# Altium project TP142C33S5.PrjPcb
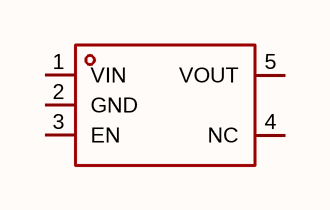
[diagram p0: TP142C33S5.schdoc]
1 sheet, 1 parts. Net scope: global (net labels, ports and power ports of the same name join across sheets).

## Sheet TP142C33S5.schdoc
size 127 x 101 mm

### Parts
U?  tp142c33s5  [SOT-23-5_L2.9-W1.6-P0.95-LS2.8-BR]  (value not drawn)

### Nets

Not connected (* = marked no-connect by the designer): U? 1(VIN) 2(GND) 3(EN) 4(NC) 5(VOUT)

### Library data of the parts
U? = tp142c33s5: 输出极性:正极;工作电压:5.5V;输出电压:3.3V;输出电流:450mA;电源纹波抑制比(PSRR):80dB@(100Hz);输出类型:固定;; Manufacturer: TECH PUBLIC(台舟); AddInBom: yes; ModelId: 7ba65df16e7b4570af156e925f9c37fe; ModelTransform: 114.173,114.173,0,90,0,0,0,0,0; Output Configuration: 正极; Voltage - Supply: 5.5V; Output Voltage: 3.3V; Output Current: 450mA; Voltage Dropout: 180mV@(300mA); standby current: 2uA; Noise: 155uVrms; Output Type: 固定; Number of Outputs: 1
